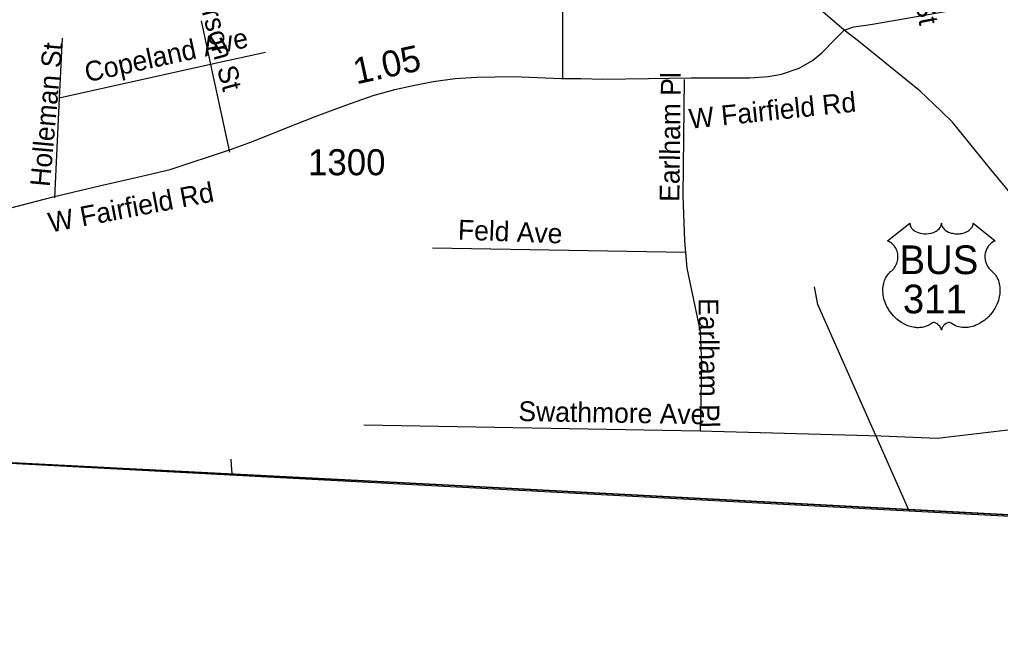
# Model space of a CAD drawing. Extents: x 1662474 to 1856135, y 779280 to 917889.
# Drawn here: x 1705150 to 1709856, y 789954 to 792888 of the extents above; entities that cross this region are included whole.
import ezdxf

# ---------------------------------------------------------------- set-up
doc = ezdxf.new("R2010")
doc.units = 0
for name, color, linetype in [('Exist Boundary Political City Limit New', 7, 'Continuous'), ('Exist Boundary Political CountyLine', 7, 'Continuous'), ('Exist Hydrographic Misc Water Feature', 7, 'Continuous'), ('Exist Road Non-System Type 51', 7, 'Continuous'), ('Exist Road Non-System Type 51 Label', 7, 'Continuous'), ('Exist Road Primary NC Attributed', 7, 'Continuous'), ('Exist Road Primary US Shield CELL', 7, 'Continuous'), ('Exist Road Primary US Shield Number Label', 7, 'Continuous'), ('Exist Road Primary US UnDivided 4 Lane Attributed', 7, 'Continuous'), ('Exist Road Secondary Mileage Hundredths English Label', 7, 'Continuous'), ('Exist Road Secondary Type 51 Attributed', 7, 'Continuous'), ('Exist Road Secondary Type 51 Label', 7, 'Continuous'), ('Exist Road Secondary Type 51 Number Label', 7, 'Continuous'), ('Map Preparation Boundary City Limit Buffer Line', 7, 'Continuous')]:
    doc.layers.add(name, color=color, linetype=linetype)

msp = doc.modelspace()

# ---------------------------------------------------------------- linework, layer by layer
at = {"layer": 'Exist Boundary Political City Limit New'}
for points in [[(1704145.4, 790811.2), (1704145.4, 790811.2), (1707146.4, 790657.5), (1711557, 790424.6)], [(1711562.1, 790424.3), (1707146.4, 790657.5), (1704145.4, 790811.2)]]:
    msp.add_lwpolyline(points, dxfattribs=at)
at = {"layer": 'Exist Boundary Political CountyLine'}
msp.add_lwpolyline([(1690037.5, 791664.5), (1701364.2, 790957.5), (1714716, 790252.3), (1740499.2, 788706.5), (1750629.1, 788065.3), (1759370.2, 787540.1), (1762189.4, 787333), (1768414.3, 786933.6), (1776472.8, 786425.7), (1794607.1, 785397.2), (1814974.6, 784258.7), (1839558.3, 782880.6)], dxfattribs=at)
at = {"layer": 'Exist Hydrographic Misc Water Feature'}
for points in [[(1709418.4, 790532.1), (1708980, 791521.1), (1708964, 791606.7)], [(1706170.4, 790703.7), (1706167.8, 790727.5), (1706164.4, 790779.6)]]:
    msp.add_lwpolyline(points, dxfattribs=at)
at = {"layer": 'Exist Road Non-System Type 51'}
for p, q in [((1707754.1, 793026.1), (1707754.1, 792603.8)), ((1706021.4, 792881.8), (1706066, 792671.8)), ((1705353.6, 792798.5), (1705340, 792510.6)), ((1706329.5, 792730.2), (1706066, 792671.8)), ((1706066, 792671.8), (1705340, 792510.6)), ((1706066, 792671.8), (1706156.2, 792252.6)), ((1705340, 792510.6), (1705317.1, 792033.4)), ((1708344.6, 791771.2), (1707131.1, 791791.4)), ((1708414.8, 790913.5), (1706801.1, 790942.4))]:
    msp.add_line(p, q, dxfattribs=at)
for points in [[(1708337.9, 792600.4), (1708331.6, 792043.2), (1708340, 791826.9), (1708344.6, 791771.2)], [(1708344.6, 791771.2), (1708351.8, 791696.4), (1708414.8, 791391.8), (1708421.1, 791232.9), (1708414.8, 790913.5)], [(1710123.4, 790945.8), (1709552, 790879.4), (1709281.9, 790889.4), (1708414.8, 790913.5)]]:
    msp.add_lwpolyline(points, dxfattribs=at)
at = {"layer": 'Exist Road Primary NC Attributed'}
msp.add_lwpolyline([(1709106, 792836.9), (1709153, 792852.6), (1709232.7, 792864.3), (1709435.3, 792898.7), (1709810.5, 792964.2), (1710227.5, 793013.7)], dxfattribs=at)
at = {"layer": 'Exist Road Primary US Shield CELL'}
msp.add_lwpolyline([(1709420.8, 791911.2), (1709421.1, 791906.8), (1709422.1, 791901.5), (1709422.9, 791898.8), (1709425.4, 791893.7), (1709429.4, 791887.6), (1709435, 791881.6), (1709441.4, 791876.4), (1709445.6, 791873.7), (1709452.9, 791869.8), (1709461.1, 791866.3), (1709470.3, 791863.7), (1709479.6, 791861.8), (1709489.8, 791860.7), (1709500, 791860.5), (1709510.9, 791861.3), (1709522.9, 791863.6), (1709528.5, 791865.1), (1709534.7, 791867.2), (1709540.5, 791869.6), (1709546.8, 791873), (1709551.9, 791876.2), (1709555.9, 791879.1), (1709561.6, 791884.5), (1709566, 791890.1), (1709567.9, 791893.3), (1709569.6, 791896.3), (1709571.8, 791902.7), (1709572.4, 791905.5), (1709572.9, 791911.4), (1709573.2, 791906.4), (1709573.7, 791903.4), (1709574.6, 791900.4), (1709575.8, 791897.2), (1709578.1, 791892.6), (1709580.6, 791888.9), (1709585.3, 791883.3), (1709588.3, 791880.5), (1709591, 791878.3), (1709598.2, 791873.4), (1709606.6, 791869.1), (1709610.8, 791867.3), (1709615, 791865.8), (1709620.4, 791864.1), (1709626, 791862.8), (1709631.5, 791861.9), (1709637.2, 791861), (1709643, 791860.6), (1709647.7, 791860.5), (1709653.5, 791860.5), (1709658.8, 791860.9), (1709664.2, 791861.5), (1709670.3, 791862.5), (1709675.1, 791863.6), (1709681.5, 791865.3), (1709687.3, 791867.3), (1709692.4, 791869.5), (1709699, 791873), (1709704.3, 791876.3), (1709708.2, 791879.4), (1709712.8, 791883.7), (1709717.2, 791888.8), (1709719.8, 791892.5), (1709721.6, 791896.3), (1709723.3, 791900.4), (1709724.3, 791904.6), (1709724.9, 791908.3), (1709725, 791911.5), (1709831.2, 791826.8), (1709828.7, 791825.9), (1709823, 791823), (1709818.4, 791820.3), (1709811.1, 791815.2), (1709807.9, 791812.4), (1709804.8, 791809.4), (1709801.9, 791806.3), (1709799.4, 791803.3), (1709796.3, 791799.1), (1709793.5, 791794.8), (1709790.8, 791790.1), (1709788.8, 791786), (1709785.6, 791777.5), (1709784, 791772.1), (1709783, 791767.5), (1709781.7, 791758), (1709781.4, 791753.5), (1709781.4, 791749), (1709781.7, 791744.3), (1709782.1, 791739.8), (1709782.9, 791735.1), (1709783.7, 791730.9), (1709785, 791725.8), (1709786.9, 791719.9), (1709789.2, 791714.2), (1709794.1, 791705), (1709800.3, 791695.6), (1709804.8, 791690.3), (1709809.2, 791685.8), (1709815.7, 791680.2), (1709819.3, 791677.1), (1709823.4, 791673), (1709830, 791665.3), (1709832.7, 791661.7), (1709835.4, 791657.6), (1709838, 791653.4), (1709840.5, 791648.8), (1709842.5, 791644.9), (1709846.2, 791635.8), (1709848.9, 791626.9), (1709850.2, 791622.3), (1709852.2, 791611.9), (1709852.9, 791606.7), (1709853.7, 791596.5), (1709853.8, 791584.2), (1709852.8, 791572.5), (1709850.6, 791558.9), (1709848.8, 791550.8), (1709846, 791541.3), (1709843.3, 791533), (1709838.5, 791520.9), (1709834.2, 791512.1), (1709828.6, 791501.8), (1709824.7, 791495.6), (1709820.3, 791489), (1709814.7, 791481.3), (1709808.2, 791473.1), (1709800.3, 791464.5), (1709794, 791458.2), (1709785.7, 791450.8), (1709780.7, 791446.6), (1709773.5, 791441.2), (1709763.7, 791434.7), (1709754.1, 791429.1), (1709745.8, 791424.9), (1709738.6, 791421.8), (1709729.1, 791418.2), (1709713.5, 791413.8), (1709707.7, 791412.7), (1709701, 791411.7), (1709694.6, 791411), (1709688.5, 791410.6), (1709680.2, 791410.6), (1709672, 791411.3), (1709664.2, 791412.4), (1709656.1, 791414.1), (1709647.6, 791416.6), (1709639.9, 791419.6), (1709632.1, 791423.5), (1709619, 791431.7), (1709615.2, 791433.8), (1709613.1, 791434.3), (1709608, 791434.6), (1709603.2, 791433.6), (1709598.3, 791431.6), (1709595.4, 791430.1), (1709591.4, 791427.5), (1709588.4, 791425.1), (1709584.8, 791421.6), (1709582.3, 791418.7), (1709580.4, 791416.5), (1709576.7, 791410.6), (1709575.3, 791407.9), (1709574, 791404.3), (1709572.7, 791399), (1709571.1, 791405.7), (1709569.1, 791410.1), (1709566.9, 791413.8), (1709564.5, 791417.2), (1709560.8, 791421.4), (1709557.5, 791424.6), (1709553.5, 791427.9), (1709549.2, 791430.5), (1709545.8, 791432.2), (1709542.6, 791433.4), (1709538.8, 791434.4), (1709535.7, 791434.6), (1709533.1, 791434.6), (1709529.6, 791433.8), (1709524.7, 791430.3), (1709520.2, 791427.2), (1709515.2, 791424.1), (1709509.3, 791420.9), (1709505, 791418.9), (1709499.9, 791416.9), (1709493.8, 791414.9), (1709487.3, 791413.2), (1709480.6, 791411.9), (1709474.7, 791411), (1709468.4, 791410.4), (1709462.6, 791410.2), (1709456.7, 791410.3), (1709451.1, 791410.7), (1709444.6, 791411.3), (1709436.6, 791412.5), (1709429.9, 791414), (1709422.9, 791415.9), (1709415.7, 791418.1), (1709408, 791421.1), (1709398.3, 791425.3), (1709391.6, 791428.7), (1709381, 791434.8), (1709368.6, 791443.4), (1709359.2, 791451), (1709352.3, 791457.2), (1709342.2, 791467.5), (1709336.3, 791474.3), (1709326.9, 791486.3), (1709321, 791495), (1709317.1, 791501.5), (1709311.5, 791511.8), (1709308.4, 791518.2), (1709304.3, 791527.6), (1709301.2, 791536.2), (1709298.5, 791544.4), (1709297.1, 791549.6), (1709295.1, 791558.7), (1709293.9, 791565.2), (1709292.7, 791574), (1709292, 791583.4), (1709291.9, 791592), (1709292.1, 791599.2), (1709293, 791607.5), (1709294.4, 791616.4), (1709296.1, 791624), (1709297.6, 791629.4), (1709299.9, 791636.1), (1709302.8, 791643.4), (1709306.4, 791650.5), (1709309.7, 791656.3), (1709313.9, 791662.6), (1709318.1, 791667.9), (1709323.5, 791673.8), (1709329.1, 791679.2), (1709334.3, 791683.4), (1709340.5, 791689.5), (1709343.7, 791693.1), (1709347.5, 791698.2), (1709350.6, 791702.9), (1709353.1, 791707.1), (1709356.3, 791713.3), (1709358.2, 791718), (1709360.7, 791725.1), (1709361.9, 791730.2), (1709363.2, 791736.6), (1709364, 791742.7), (1709364.3, 791750.3), (1709364.1, 791756.6), (1709363.3, 791764), (1709361.9, 791771), (1709360.2, 791777.1), (1709357.6, 791784.2), (1709355.2, 791789.3), (1709351.1, 791796.3), (1709346.6, 791802.8), (1709341.9, 791808), (1709337.2, 791812.7), (1709332.7, 791816.3), (1709328.4, 791819.3), (1709323, 791822.6), (1709317.8, 791825.2), (1709314.5, 791826.5)], close=True, dxfattribs=at)
at = {"layer": 'Exist Road Primary US UnDivided 4 Lane Attributed'}
for points in [[(1709106, 792836.9), (1708244.2, 793579.6), (1707900.6, 793855.5), (1707749.3, 793987.3), (1707630, 794106.5), (1707578, 794164.6), (1707541.3, 794210.5), (1707523, 794253.3), (1707498.5, 794305.3), (1707480.1, 794354.2), (1707449.6, 794467.3), (1707397.5, 794666.1), (1707351.7, 794852.6), (1707281.3, 795146.1), (1707226.2, 795354), (1707146.7, 795681.2), (1707119.2, 795757.6), (1707085.5, 795818.8), (1707001, 795965.8)], [(1711220.5, 790437), (1711026, 790676.9), (1710783.2, 790974.8), (1710511.9, 791312.5), (1710389, 791458.9), (1710181.8, 791717), (1710003.5, 791936), (1709803.6, 792177.6), (1709625.7, 792396.6), (1709570.2, 792450.6), (1709470.9, 792543.9), (1709174.9, 792783.7), (1709106, 792836.9)]]:
    msp.add_lwpolyline(points, dxfattribs=at)
at = {"layer": 'Exist Road Secondary Type 51 Attributed'}
msp.add_lwpolyline([(1705108.1, 791984.8), (1705317.7, 792039.3), (1705539, 792092.8), (1705714.5, 792131.7), (1705872.5, 792168.8), (1706160.8, 792264.3), (1706266.5, 792303.4), (1706422.7, 792365.4), (1706572, 792425.1), (1706714.5, 792477.9), (1706845.4, 792523.8), (1706950.2, 792553.1), (1707030.1, 792570.5), (1707134.4, 792591.3), (1707238.7, 792605.2), (1707343, 792612.2), (1707518.9, 792615.6), (1707748.3, 792605.2), (1707843.9, 792605.2), (1707948.2, 792601.7), (1708167.2, 792605.2), (1708372.4, 792608.9), (1708653, 792608.9), (1708742.1, 792615.5), (1708804.8, 792625.4), (1708890.7, 792655), (1708953.4, 792691.3), (1708999.6, 792727.6), (1709062.3, 792793.6), (1709106, 792836.9)], dxfattribs=at)
at = {"layer": 'Map Preparation Boundary City Limit Buffer Line'}
for points in [[(1704145.4, 790811.2), (1704145.4, 790811.2), (1707146.4, 790657.5), (1711557, 790424.6)], [(1711562.1, 790424.3), (1707146.4, 790657.5), (1704145.4, 790811.2)]]:
    msp.add_lwpolyline(points, dxfattribs=at)

# ---------------------------------------------------------------- texts
at = {"layer": 'Exist Road Non-System Type 51 Label'}
for s, rotation, p in [('Bellemeade St', 281.2302, (1709307.3, 793666)), ('Emerson St', 284.8945, (1705956.1, 793179.2)), ('Copeland Ave', 12.3023, (1705473, 792586.8)), ('Holleman St', 84.8322, (1705294.1, 792083.5)), ('Earlham Pl', 89.3388, (1708315.2, 792013.5)), ('Feld Ave', 357.771, (1707251.5, 791833.3)), ('Earlham Pl', 270.5016, (1708407.1, 791551.8)), ('Swathmore Ave', 358.9871, (1707542.5, 790962.8))]:
    msp.add_text(s, height=95, rotation=rotation, dxfattribs=at).set_placement(p)
at = {"layer": 'Exist Road Primary US Shield Number Label'}
for s, p in [('BUS', (1709371.7, 791667.1)), ('311', (1709387.9, 791479.1))]:
    msp.add_text(s, height=137.5, dxfattribs=at).set_placement(p)
at = {"layer": 'Exist Road Secondary Mileage Hundredths English Label'}
msp.add_text('1.05', height=125, rotation=12.2589, dxfattribs=at).set_placement((1706765.5, 792576.9))
at = {"layer": 'Exist Road Secondary Type 51 Label'}
for rotation, p in [(5.9138, (1708366.5, 792364)), (10.7669, (1705297.1, 791866.2))]:
    msp.add_text('W Fairfield Rd', height=95, rotation=rotation, dxfattribs=at).set_placement(p)
at = {"layer": 'Exist Road Secondary Type 51 Number Label'}
msp.add_text('1300', height=125, dxfattribs=at).set_placement((1706533.4, 792141.2))

doc.saveas('drawing.dxf')
